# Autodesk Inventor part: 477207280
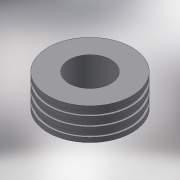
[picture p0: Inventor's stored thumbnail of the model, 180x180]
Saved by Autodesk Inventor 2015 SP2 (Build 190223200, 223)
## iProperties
Created: 2017-08
Part Number: 477207280
Material: Generic
Description: PLASSON MAN HOLE ADAPTOR 280
Document SubType Name: Modeling
Designer: Кирилл
Density: 1 g/cm^3
Appearance: Default
Author: Кирилл
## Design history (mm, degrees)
derived "37020-477207.ipt"
feature "Solid1::37020-477207.ipt"
tag "TaggingFeature1"
body "Solid1"
other parameters: "d0" = 135, "d3" = 247, "d6" = 39, "L_" = 135, "d_1" = 247, "H_" = 39
